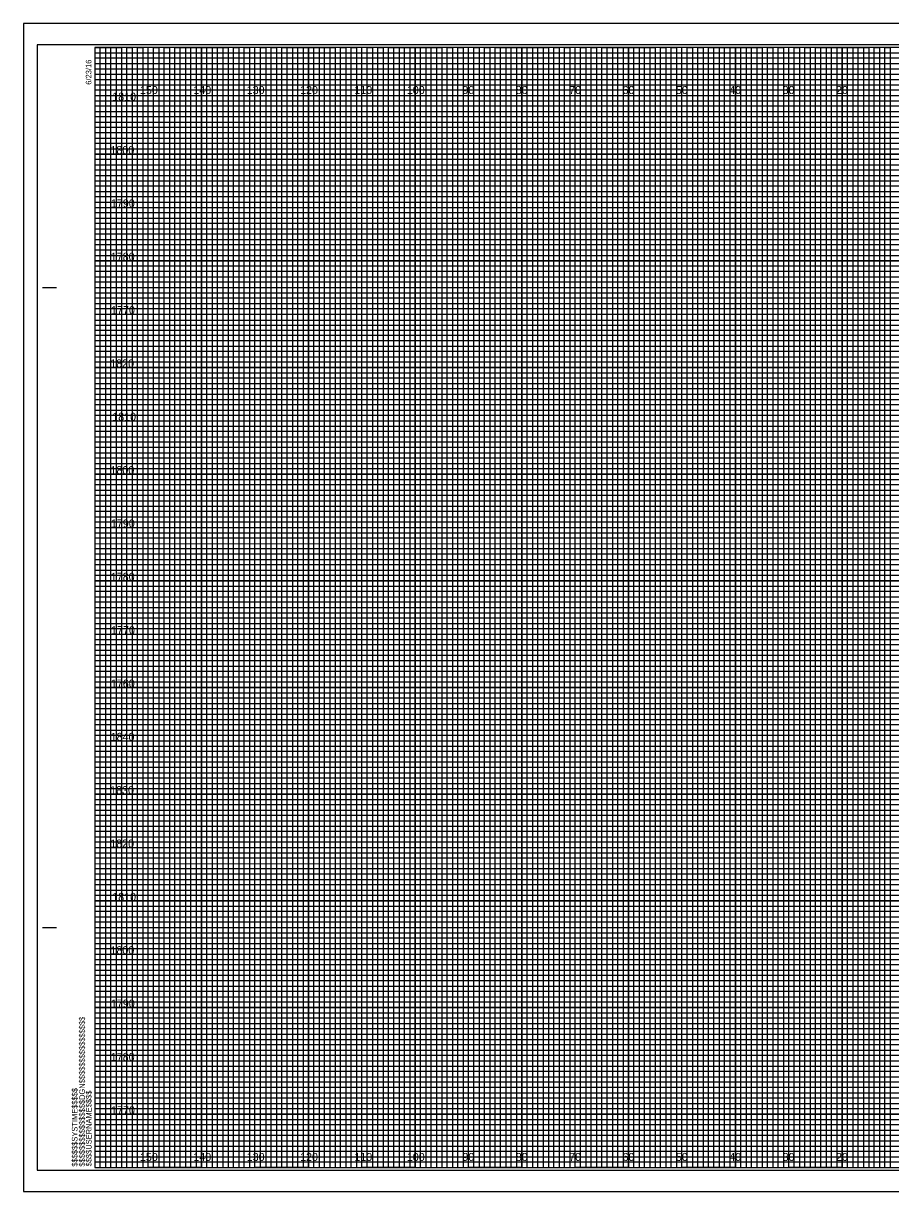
# Model space of a CAD drawing. Extents: x -163 to 174, y 11 to 1110.
# Drawn here: x -162.9 to -0.4, y 231.2 to 450.2 of the extents above; entities that cross this region are included whole.
import ezdxf

# ---------------------------------------------------------------- set-up
doc = ezdxf.new("R2010")
doc.units = 0
for name, color, linetype in [('Prop XS DDE', 7, 'Continuous'), ('Prop XS Earthwork Shape', 7, 'Continuous'), ('Prop XS Elevation Labels', 7, 'Continuous'), ('Sheet Cross Section CELL', 7, 'Continuous'), ('Sheet Cross Section Grid Middle CELL', 7, 'Continuous'), ('Sheet Cross Section Grid Minor 1 CELL', 7, 'Continuous'), ('Sheet Cross Section Grid Minor 2 CELL', 7, 'Continuous'), ('Sheet Cutting Line CELL', 7, 'Continuous'), ('Sheet DOT Grid CELL', 7, 'Continuous'), ('Sheet Plot Border Inside CELL', 7, 'Continuous'), ('Sheet Plot Border Outside CELL', 7, 'Continuous')]:
    doc.layers.add(name, color=color, linetype=linetype)

msp = doc.modelspace()

# ---------------------------------------------------------------- linework, layer by layer
at = {"layer": 'Prop XS DDE'}
for p, q in [((-139.53, 445.7), (-149.53, 445.7)), ((-139.53, 235.7), (-139.53, 445.7)), ((-119.53, 445.7), (-129.53, 445.7)), ((-129.53, 445.7), (-129.53, 235.7)), ((-119.53, 235.7), (-119.53, 445.7)), ((-99.53, 445.7), (-109.53, 445.7)), ((-109.53, 445.7), (-109.53, 235.7)), ((-99.53, 235.7), (-99.53, 445.7)), ((-79.53, 445.7), (-89.53, 445.7)), ((-89.53, 445.7), (-89.53, 235.7)), ((-79.53, 235.7), (-79.53, 445.7)), ((-59.53, 445.7), (-69.53, 445.7)), ((-69.53, 445.7), (-69.53, 235.7)), ((-59.53, 235.7), (-59.53, 445.7)), ((-39.53, 445.7), (-49.53, 445.7)), ((-49.53, 445.7), (-49.53, 235.7)), ((-39.53, 235.7), (-39.53, 445.7)), ((-19.53, 445.7), (-29.53, 445.7)), ((-29.53, 445.7), (-29.53, 235.7)), ((-19.53, 235.7), (-19.53, 445.7)), ((0.47, 445.7), (-9.53, 445.7)), ((-9.53, 445.7), (-9.53, 235.7)), ((-129.53, 235.7), (-139.53, 235.7)), ((-109.53, 235.7), (-119.53, 235.7)), ((-89.53, 235.7), (-99.53, 235.7)), ((-69.53, 235.7), (-79.53, 235.7)), ((-49.53, 235.7), (-59.53, 235.7)), ((-29.53, 235.7), (-39.53, 235.7)), ((-9.53, 235.7), (-19.53, 235.7))]:
    msp.add_line(p, q, dxfattribs=at)
for points in [[(-149.53, 435.7), (170.47, 435.7), (170.47, 425.7), (-149.53, 425.7)], [(-149.53, 415.7), (170.47, 415.7), (170.47, 405.7), (-149.53, 405.7)], [(-149.53, 395.7), (170.47, 395.7), (170.47, 385.7), (-149.53, 385.7)], [(-149.53, 375.7), (170.47, 375.7), (170.47, 365.7), (-149.53, 365.7)], [(-149.53, 355.7), (170.47, 355.7), (170.47, 345.7), (-149.53, 345.7)], [(-149.53, 335.7), (170.47, 335.7), (170.47, 325.7), (-149.53, 325.7)], [(-149.53, 315.7), (170.47, 315.7), (170.47, 305.7), (-149.53, 305.7)], [(-149.53, 295.7), (170.47, 295.7), (170.47, 285.7), (-149.53, 285.7)], [(-149.53, 275.7), (170.47, 275.7), (170.47, 265.7), (-149.53, 265.7)], [(-149.53, 255.7), (170.47, 255.7), (170.47, 245.7), (-149.53, 245.7)]]:
    msp.add_lwpolyline(points, dxfattribs=at)
at = {"layer": 'Sheet Cross Section CELL'}
for p, q in [((-159.33, 400.7), (-156.83, 400.7)), ((-159.23, 400.7), (-156.73, 400.7)), ((-159.33, 280.7), (-156.83, 280.7)), ((-159.23, 280.7), (-156.73, 280.7)), ((-149.53, 235.7), (-149.53, 235.7)), ((-149.53, 235.7), (-149.53, 235.7)), ((-149.53, 235.7), (-149.53, 235.7)), ((-149.53, 235.7), (-149.53, 235.7)), ((-149.53, 235.7), (-149.53, 235.7)), ((-149.53, 235.7), (-149.53, 235.7)), ((-149.53, 235.7), (-149.53, 235.7))]:
    msp.add_line(p, q, dxfattribs=at)
msp.add_lwpolyline([(170.47, 445.7), (-149.53, 445.7), (-149.53, 235.7), (170.47, 235.7)], close=True, dxfattribs=at)
at = {"layer": 'Sheet Cross Section Grid Middle CELL'}
for points in [[(-149.53, 445.7), (-144.53, 445.7), (-144.53, 235.7), (-134.53, 235.7), (-134.53, 445.7), (-124.53, 445.7), (-124.53, 235.7), (-114.53, 235.7), (-114.53, 445.7), (-104.53, 445.7), (-104.53, 235.7), (-94.53, 235.7), (-94.53, 445.7), (-84.53, 445.7), (-84.53, 235.7), (-74.53, 235.7), (-74.53, 445.7), (-64.53, 445.7), (-64.53, 235.7), (-54.53, 235.7), (-54.53, 445.7), (-44.53, 445.7), (-44.53, 235.7), (-34.53, 235.7), (-34.53, 445.7), (-24.53, 445.7), (-24.53, 235.7), (-14.53, 235.7), (-14.53, 445.7), (-4.53, 445.7), (-4.53, 235.7), (5.47, 235.7)], [(-149.53, 440.7), (125.47, 440.7)], [(-149.53, 420.7), (170.47, 420.7), (170.47, 430.7), (-149.53, 430.7)], [(-149.53, 400.7), (170.47, 400.7), (170.47, 410.7), (-149.53, 410.7)], [(-149.53, 380.7), (170.47, 380.7), (170.47, 390.7), (-149.53, 390.7)], [(-149.53, 360.7), (170.47, 360.7), (170.47, 370.7), (-149.53, 370.7)], [(-149.53, 340.7), (170.47, 340.7), (170.47, 350.7), (-149.53, 350.7)], [(-149.53, 320.7), (170.47, 320.7), (170.47, 330.7), (-149.53, 330.7)], [(-149.53, 300.7), (170.47, 300.7), (170.47, 310.7), (-149.53, 310.7)], [(-149.53, 280.7), (170.47, 280.7), (170.47, 290.7), (-149.53, 290.7)], [(-149.53, 260.7), (170.47, 260.7), (170.47, 270.7), (-149.53, 270.7)], [(-149.53, 240.7), (170.47, 240.7), (170.47, 250.7), (-149.53, 250.7)]]:
    msp.add_lwpolyline(points, dxfattribs=at)
at = {"layer": 'Sheet Cross Section Grid Minor 1 CELL'}
for p, q in [((-149.53, 444.7), (110.47, 444.7)), ((110.47, 443.68), (-149.53, 443.68)), ((-149.53, 443.68), (-149.53, 442.7)), ((-149.53, 442.7), (110.47, 442.7)), ((110.47, 441.59), (-149.53, 441.59)), ((-149.53, 441.59), (-149.53, 439.7)), ((-149.53, 439.7), (170.47, 439.7))]:
    msp.add_line(p, q, dxfattribs=at)
for points in [[(-149.53, 438.7), (120.47, 438.7), (170.47, 438.7), (170.47, 437.7), (-149.53, 437.7)], [(-149.53, 436.7), (170.47, 436.7), (170.47, 434.7), (-149.53, 434.7)], [(-149.53, 433.7), (170.47, 433.7), (170.47, 432.7), (-149.53, 432.68)], [(-149.53, 431.7), (170.47, 431.7), (170.47, 429.7), (-149.53, 429.7)], [(-149.53, 428.7), (170.47, 428.7), (170.47, 427.7), (-149.53, 427.7)], [(-149.53, 426.7), (170.47, 426.7), (170.47, 424.7), (-149.53, 424.7)], [(-149.53, 423.7), (170.47, 423.7), (170.47, 422.7), (-149.53, 422.7)], [(-149.53, 421.7), (170.47, 421.7), (170.47, 419.7), (-149.53, 419.7)], [(-149.53, 418.7), (170.47, 418.7), (170.47, 417.7), (-149.53, 417.7)], [(-149.53, 416.7), (170.47, 416.7), (170.47, 414.7), (-149.53, 414.7)], [(-149.53, 413.7), (170.47, 413.7), (170.47, 412.7), (-149.53, 412.7)], [(-149.53, 411.7), (170.47, 411.7), (170.47, 409.65), (170.47, 408.7), (170.47, 407.7), (-149.53, 407.7)], [(-149.53, 409.7), (170.47, 409.7), (170.47, 408.7), (-149.53, 408.7)], [(-149.53, 406.7), (170.47, 406.7), (170.47, 404.7), (-149.53, 404.73)], [(-149.53, 404.73), (170.47, 404.7), (170.47, 403.7), (-149.53, 403.7)], [(-149.53, 402.7), (170.47, 402.7), (170.47, 401.7), (-149.53, 401.7)], [(-149.53, 399.7), (170.47, 399.7), (170.47, 398.7), (-149.53, 398.7)], [(-149.53, 397.7), (170.47, 397.7), (170.47, 396.7), (-149.53, 396.7)], [(-149.6, 394.59), (170.47, 394.59), (170.47, 393.58), (-149.6, 393.58)], [(-149.53, 392.7), (170.47, 392.7), (170.47, 391.7), (-149.53, 391.7)], [(-149.53, 389.7), (170.47, 389.7), (170.47, 388.7), (-149.53, 388.7)], [(-149.53, 387.7), (170.47, 387.7), (170.47, 386.7), (-149.53, 386.7)], [(-149.53, 384.7), (170.47, 384.7), (170.47, 383.7), (-149.53, 383.7)], [(-149.53, 382.7), (170.47, 382.7), (170.47, 381.7), (-149.53, 381.7)], [(-149.53, 379.7), (170.47, 379.7), (170.47, 378.7), (-149.53, 378.7)], [(-149.53, 377.7), (170.47, 377.7), (170.47, 376.7), (-149.53, 376.7)], [(-149.53, 374.7), (170.47, 374.7), (170.46, 373.68), (-149.53, 373.7)], [(-149.53, 372.7), (170.47, 372.7), (170.47, 371.7), (-149.53, 371.7)], [(-149.53, 369.7), (170.47, 369.7), (170.47, 368.7), (-149.53, 368.7)], [(-149.53, 367.7), (170.47, 367.7), (170.47, 366.7), (-149.53, 366.7)], [(-149.53, 364.7), (170.47, 364.7), (170.47, 363.7), (-149.53, 363.7)], [(-149.53, 362.7), (170.47, 362.7), (170.47, 361.7), (-149.53, 361.7)], [(-149.53, 359.7), (170.47, 359.7), (170.47, 358.7), (-149.53, 358.7)], [(-149.53, 357.7), (170.47, 357.7), (170.47, 356.7), (-149.53, 356.7)], [(-149.53, 354.7), (170.47, 354.7), (170.47, 353.7), (-149.53, 353.7)], [(-149.53, 352.69), (170.54, 352.61), (170.47, 351.7), (-149.53, 351.7)], [(-149.53, 349.7), (170.47, 349.7), (170.47, 348.7), (-149.53, 348.7)], [(-149.53, 347.7), (170.47, 347.7), (170.47, 346.7), (-149.53, 346.7)], [(-149.53, 344.7), (170.47, 344.7), (170.47, 343.7), (-149.53, 343.7)], [(-149.53, 342.7), (170.47, 342.7), (170.47, 341.7), (-149.53, 341.7)], [(-149.53, 339.7), (170.47, 339.7), (170.47, 338.7), (-149.53, 338.7)], [(-149.53, 337.7), (170.47, 337.7), (170.47, 336.7), (-149.53, 336.7)], [(-149.53, 334.7), (170.47, 334.7), (170.47, 333.7), (-149.53, 333.7)], [(-149.53, 332.7), (170.47, 332.7), (170.47, 331.7), (-149.53, 331.7)], [(-149.53, 329.7), (170.47, 329.7), (170.47, 328.7), (-149.53, 328.7)], [(-149.53, 327.7), (170.47, 327.7), (170.47, 326.7), (-149.53, 326.7)], [(-149.53, 324.7), (170.47, 324.7), (170.47, 323.7), (-149.53, 323.7)], [(-149.53, 322.7), (170.47, 322.7), (170.47, 321.7), (-149.53, 321.7)], [(-149.53, 319.7), (170.47, 319.7), (170.47, 318.7), (-149.53, 318.7)], [(-149.53, 317.7), (170.47, 317.7), (170.47, 316.7), (-149.53, 316.7)], [(-149.53, 314.7), (170.47, 314.7), (170.46, 313.68), (-149.53, 313.7)], [(-149.53, 312.7), (170.47, 312.7), (170.47, 311.7), (-149.53, 311.7)], [(-149.53, 309.7), (170.47, 309.7), (170.47, 308.7), (-149.53, 308.7)], [(-149.53, 307.7), (170.47, 307.7), (170.47, 306.7), (-149.53, 306.7)], [(-149.53, 304.7), (170.47, 304.7), (170.47, 303.7), (-149.53, 303.7)], [(-149.53, 302.7), (170.47, 302.7), (170.47, 301.7), (-149.53, 301.7)], [(-149.53, 299.7), (170.47, 299.7), (170.47, 298.7), (-149.53, 298.7)], [(-149.53, 297.7), (170.47, 297.7), (170.47, 296.7), (-149.53, 296.7)], [(-149.53, 294.7), (170.47, 294.7), (170.47, 293.7), (-149.53, 293.7)], [(-149.53, 292.69), (170.54, 292.61), (170.47, 291.7), (-149.53, 291.7)], [(-149.53, 289.7), (170.47, 289.7), (170.47, 288.7), (-149.53, 288.7)], [(-149.53, 287.7), (170.47, 287.7), (170.47, 286.7), (-149.53, 286.7)], [(-149.53, 284.7), (170.47, 284.7), (170.47, 283.7), (-149.53, 283.7)], [(-149.53, 282.7), (170.47, 282.7), (170.47, 281.7), (-149.53, 281.7)], [(-149.53, 279.7), (170.47, 279.7), (170.47, 278.7), (-149.53, 278.7)], [(-149.53, 277.7), (170.47, 277.7), (170.47, 276.7), (-149.53, 276.7)], [(-149.53, 274.7), (170.47, 274.7), (170.47, 273.7), (-149.53, 273.7)], [(-149.53, 272.7), (170.47, 272.7), (170.47, 271.7), (-149.53, 271.7)], [(-149.53, 269.7), (170.47, 269.7), (170.47, 268.7), (-149.53, 268.7)], [(-149.53, 267.7), (170.47, 267.7), (170.47, 266.7), (-149.53, 266.7)], [(-149.53, 264.7), (170.47, 264.7), (170.47, 263.7), (-149.53, 263.7)], [(-149.53, 262.7), (170.47, 262.7), (170.47, 261.7), (-149.53, 261.7)], [(-149.53, 259.7), (170.47, 259.7), (170.47, 258.7), (-149.53, 258.7)], [(-149.53, 257.7), (170.47, 257.7), (170.47, 256.7), (-149.53, 256.7)], [(-149.53, 254.7), (170.47, 254.7), (170.47, 253.7), (-149.53, 253.7)], [(-149.53, 252.7), (170.47, 252.7), (170.47, 251.7), (-149.53, 251.7)], [(-149.53, 249.7), (170.47, 249.7), (170.47, 248.7), (-149.53, 248.7)], [(-149.53, 247.7), (170.47, 247.7), (170.47, 246.7), (-149.53, 246.7)], [(-149.53, 244.7), (170.47, 244.7), (170.47, 243.7), (-149.53, 243.7)], [(-149.53, 242.7), (170.47, 242.7), (170.47, 241.7), (-149.53, 241.7)], [(-149.53, 239.7), (170.47, 239.7), (170.47, 238.7), (-149.53, 238.7)], [(-149.53, 237.7), (170.47, 237.7), (170.47, 236.7), (-149.53, 236.7)]]:
    msp.add_lwpolyline(points, dxfattribs=at)
at = {"layer": 'Sheet Cross Section Grid Minor 2 CELL'}
for points in [[(-149.53, 235.7), (-148.53, 235.7), (-148.53, 445.7), (-147.53, 445.7), (-147.53, 235.7)], [(-147.53, 235.7), (-146.53, 235.7), (-146.53, 445.7), (-145.53, 445.7), (-145.53, 235.7)], [(-144.53, 235.7), (-143.53, 235.7), (-143.53, 445.7), (-142.53, 445.7), (-142.53, 235.7)], [(-142.53, 235.7), (-141.53, 235.7), (-141.53, 445.7), (-140.53, 445.7), (-140.53, 235.7)], [(-139.53, 235.7), (-138.53, 235.7), (-138.53, 445.7), (-137.53, 445.7), (-137.53, 235.7)], [(-137.53, 235.7), (-136.53, 235.7), (-136.53, 445.7), (-135.53, 445.7), (-135.53, 235.7)], [(-134.53, 235.7), (-133.53, 235.7), (-133.53, 445.7), (-132.53, 445.7), (-132.53, 235.7)], [(-132.53, 235.7), (-131.53, 235.7), (-131.53, 445.7), (-130.53, 445.7), (-130.53, 235.7)], [(-129.53, 235.7), (-128.53, 235.7), (-128.53, 445.7), (-127.53, 445.7), (-127.53, 235.7)], [(-127.53, 235.7), (-126.53, 235.7), (-126.53, 445.7), (-125.53, 445.7), (-125.53, 235.7)], [(-124.53, 235.7), (-123.53, 235.7), (-123.53, 445.7), (-122.53, 445.7), (-122.53, 235.7)], [(-122.53, 235.7), (-121.53, 235.7), (-121.53, 445.7), (-120.53, 445.7), (-120.53, 235.7)], [(-119.53, 235.7), (-118.53, 235.7), (-118.53, 445.7), (-117.53, 445.7), (-117.53, 235.7)], [(-117.53, 235.7), (-116.53, 235.7), (-116.53, 445.7), (-115.53, 445.7), (-115.53, 235.7)], [(-114.53, 235.7), (-113.53, 235.7), (-113.53, 445.7), (-112.53, 445.7), (-112.53, 235.7)], [(-112.53, 235.7), (-111.53, 235.7), (-111.53, 445.7), (-110.53, 445.7), (-110.53, 235.7)], [(-109.53, 235.7), (-108.53, 235.7), (-108.53, 445.7), (-107.53, 445.7), (-107.53, 235.7)], [(-107.53, 235.7), (-106.53, 235.7), (-106.53, 445.7), (-105.53, 445.7), (-105.53, 235.7)], [(-104.53, 235.7), (-103.53, 235.7), (-103.53, 445.7), (-102.53, 445.7), (-102.53, 235.7)], [(-102.53, 235.7), (-101.53, 235.7), (-101.53, 445.7), (-100.53, 445.7), (-100.53, 235.7)], [(-99.53, 235.7), (-98.53, 235.7), (-98.53, 445.7), (-97.53, 445.7), (-97.53, 235.7)], [(-97.53, 235.7), (-96.53, 235.7), (-96.53, 445.7), (-95.53, 445.7), (-95.53, 235.7)], [(-94.53, 235.7), (-93.53, 235.7), (-93.53, 445.7), (-92.53, 445.7), (-92.53, 235.7)], [(-92.53, 235.7), (-91.53, 235.7), (-91.53, 445.7), (-90.53, 445.7), (-90.53, 235.7)], [(-89.53, 235.7), (-88.53, 235.7), (-88.53, 445.7), (-87.53, 445.7), (-87.53, 235.7)], [(-87.53, 235.7), (-86.53, 235.7), (-86.53, 445.7), (-85.53, 445.7), (-85.53, 235.7)], [(-84.53, 235.7), (-83.53, 235.7), (-83.53, 445.7), (-82.53, 445.7), (-82.53, 235.7)], [(-82.53, 235.7), (-81.53, 235.7), (-81.53, 445.7), (-80.53, 445.7), (-80.53, 235.7)], [(-79.53, 235.7), (-78.53, 235.7), (-78.53, 445.7), (-77.53, 445.7), (-77.53, 235.7)], [(-77.53, 235.7), (-76.53, 235.7), (-76.53, 445.7), (-75.53, 445.7), (-75.53, 235.7)], [(-74.53, 235.7), (-73.53, 235.7), (-73.53, 445.7), (-72.53, 445.7), (-72.53, 235.7)], [(-72.53, 235.7), (-71.53, 235.7), (-71.53, 445.7), (-70.53, 445.7), (-70.53, 235.7)], [(-69.53, 235.7), (-68.53, 235.7), (-68.53, 445.7), (-67.53, 445.7), (-67.53, 235.7)], [(-67.53, 235.7), (-66.53, 235.7), (-66.53, 445.7), (-65.53, 445.7), (-65.53, 235.7)], [(-64.53, 235.7), (-63.53, 235.7), (-63.53, 445.7), (-62.53, 445.7), (-62.53, 235.7)], [(-62.53, 235.7), (-61.53, 235.7), (-61.53, 445.7), (-60.53, 445.7), (-60.53, 235.7)], [(-59.53, 235.7), (-58.53, 235.7), (-58.53, 445.7), (-57.53, 445.7), (-57.53, 235.7)], [(-57.53, 235.7), (-56.53, 235.7), (-56.53, 445.7), (-55.53, 445.7), (-55.53, 235.7)], [(-54.53, 235.7), (-53.53, 235.7), (-53.53, 445.7), (-52.53, 445.7), (-52.53, 235.7)], [(-52.53, 235.7), (-51.53, 235.7), (-51.53, 445.7), (-50.53, 445.7), (-50.53, 235.7)], [(-49.53, 235.7), (-48.53, 235.7), (-48.53, 445.7), (-47.53, 445.7), (-47.53, 235.7)], [(-47.53, 235.7), (-46.53, 235.7), (-46.53, 445.7), (-45.53, 445.7), (-45.53, 235.7)], [(-44.53, 235.7), (-43.53, 235.7), (-43.53, 445.7), (-42.53, 445.7), (-42.53, 235.7)], [(-42.53, 235.7), (-41.53, 235.7), (-41.53, 445.7), (-40.53, 445.7), (-40.53, 235.7)], [(-39.53, 235.7), (-38.53, 235.7), (-38.53, 445.7), (-37.53, 445.7), (-37.53, 235.7)], [(-37.53, 235.7), (-36.53, 235.7), (-36.53, 445.7), (-35.53, 445.7), (-35.53, 235.7)], [(-34.53, 235.7), (-33.53, 235.7), (-33.53, 445.7), (-32.53, 445.7), (-32.53, 235.7)], [(-32.53, 235.7), (-31.53, 235.7), (-31.53, 445.7), (-30.53, 445.7), (-30.53, 235.7)], [(-29.53, 235.7), (-28.53, 235.7), (-28.53, 445.7), (-27.53, 445.7), (-27.53, 235.7)], [(-27.53, 235.7), (-26.53, 235.7), (-26.53, 445.7), (-25.53, 445.7), (-25.53, 235.7)], [(-24.53, 235.7), (-23.53, 235.7), (-23.53, 445.7), (-22.53, 445.7), (-22.53, 235.7)], [(-22.53, 235.7), (-21.53, 235.7), (-21.53, 445.7), (-20.53, 445.7), (-20.53, 235.7)], [(-19.53, 235.7), (-18.53, 235.7), (-18.53, 445.7), (-17.53, 445.7), (-17.53, 235.7)], [(-17.53, 235.7), (-16.53, 235.7), (-16.53, 445.7), (-15.53, 445.7), (-15.53, 235.7)], [(-14.53, 235.7), (-13.53, 235.7), (-13.53, 445.7), (-12.53, 445.7), (-12.53, 235.7)], [(-12.53, 235.7), (-11.53, 235.7), (-11.53, 445.7), (-10.53, 445.7), (-10.53, 235.7)], [(-9.53, 235.7), (-8.53, 235.7), (-8.53, 445.7), (-7.53, 445.7), (-7.53, 235.7)], [(-7.53, 235.7), (-6.53, 235.7), (-6.53, 445.7), (-5.53, 445.7), (-5.53, 235.7)], [(-4.53, 235.7), (-3.53, 235.7), (-3.53, 445.7), (-2.53, 445.7), (-2.53, 235.7)], [(-2.53, 235.7), (-1.53, 235.7), (-1.53, 445.7), (-0.53, 445.7), (-0.53, 235.7)]]:
    msp.add_lwpolyline(points, dxfattribs=at)
at = {"layer": 'Sheet Cutting Line CELL'}
for p, q in [((173.77, 450.2), (-162.93, 450.2)), ((-162.93, 450.2), (-162.93, 231.2)), ((-162.93, 231.2), (173.77, 231.2))]:
    msp.add_line(p, q, dxfattribs=at)
at = {"layer": 'Sheet DOT Grid CELL'}
for p, q in [((-139.53, 235.7), (-139.53, 445.7)), ((-129.53, 235.7), (-129.53, 445.7)), ((-119.53, 235.7), (-119.53, 445.7)), ((-109.53, 235.7), (-109.53, 445.7)), ((-99.53, 235.7), (-99.53, 445.7)), ((-89.53, 235.7), (-89.53, 445.7)), ((-79.53, 235.7), (-79.53, 445.7)), ((-69.53, 235.7), (-69.53, 445.7)), ((-59.53, 235.7), (-59.53, 445.7)), ((-49.53, 235.7), (-49.53, 445.7)), ((-39.53, 235.7), (-39.53, 445.7)), ((-29.53, 235.7), (-29.53, 445.7)), ((-19.53, 235.7), (-19.53, 445.7)), ((-9.53, 235.7), (-9.53, 445.7)), ((-149.53, 435.7), (170.47, 435.7)), ((-149.53, 425.7), (170.47, 425.7)), ((-149.53, 415.7), (170.47, 415.7)), ((-149.53, 405.7), (170.47, 405.7)), ((-149.53, 395.7), (170.47, 395.7)), ((-149.53, 385.7), (170.47, 385.7)), ((-149.53, 375.7), (170.47, 375.7)), ((-149.53, 365.7), (170.47, 365.7)), ((-149.53, 355.7), (170.47, 355.7)), ((-149.53, 345.7), (170.47, 345.7)), ((-149.53, 335.7), (170.47, 335.7)), ((-149.53, 325.7), (170.47, 325.7)), ((-149.53, 315.7), (170.47, 315.7)), ((-149.53, 305.7), (170.47, 305.7)), ((-149.53, 295.7), (170.47, 295.7)), ((-149.53, 285.7), (170.47, 285.7)), ((-149.53, 275.7), (170.47, 275.7)), ((-149.53, 265.7), (170.47, 265.7)), ((-149.53, 255.7), (170.47, 255.7)), ((-149.53, 245.7), (170.47, 245.7))]:
    msp.add_line(p, q, dxfattribs=at)
at = {"layer": 'Sheet Plot Border Inside CELL'}
msp.add_lwpolyline([(-160.33, 235.2), (172.87, 235.2), (172.87, 446.2), (-160.33, 446.2)], close=True, dxfattribs=at)
at = {"layer": 'Sheet Plot Border Outside CELL'}
msp.add_lwpolyline([(-162.93, 231.2), (173.77, 231.2), (173.77, 450.2), (-162.93, 450.2)], close=True, dxfattribs=at)

# ---------------------------------------------------------------- texts
at = {"layer": 'Prop XS Earthwork Shape'}
for s, p in [('150', (-141.08, 436.95)), ('140', (-131.08, 436.95)), ('130', (-121.08, 436.95)), ('120', (-111.08, 436.95)), ('110', (-100.91, 436.95)), ('100', (-91.08, 436.95)), ('90', (-80.67, 436.95)), ('80', (-70.67, 436.95)), ('70', (-60.67, 436.95)), ('60', (-50.67, 436.95)), ('50', (-40.67, 436.95)), ('40', (-30.67, 436.95)), ('30', (-20.67, 436.95)), ('20', (-10.67, 436.95)), ('150', (-141.08, 236.95)), ('140', (-131.08, 236.95)), ('130', (-121.08, 236.95)), ('120', (-111.08, 236.95)), ('110', (-100.91, 236.95)), ('100', (-91.08, 236.95)), ('90', (-80.67, 236.95)), ('80', (-70.67, 236.95)), ('70', (-60.67, 236.95)), ('60', (-50.67, 236.95)), ('50', (-40.67, 236.95)), ('40', (-30.67, 236.95)), ('30', (-20.67, 236.95)), ('20', (-10.67, 236.95))]:
    msp.add_text(s, height=1.5, dxfattribs=at).set_placement(p)
at = {"layer": 'Prop XS Elevation Labels'}
for s, p in [('1810', (-146.28, 435.7)), ('1800', (-146.61, 425.7)), ('1790', (-146.53, 415.7)), ('1780', (-146.55, 405.7)), ('1770', (-146.49, 395.7)), ('1820', (-146.65, 385.7)), ('1810', (-146.28, 375.7)), ('1800', (-146.61, 365.7)), ('1790', (-146.53, 355.7)), ('1780', (-146.55, 345.7)), ('1770', (-146.49, 335.7)), ('1760', (-146.53, 325.7)), ('1840', (-146.58, 315.7)), ('1830', (-146.67, 305.7)), ('1820', (-146.65, 295.7)), ('1810', (-146.28, 285.7)), ('1800', (-146.61, 275.7)), ('1790', (-146.53, 265.7)), ('1780', (-146.55, 255.7)), ('1770', (-146.49, 245.7))]:
    msp.add_text(s, height=1.5, dxfattribs=at).set_placement(p)
at = {"layer": 'Sheet Cross Section CELL'}
for s, p in [('6/23/16', (-150.18, 438.7)), ('$$$$$$$$$$$$$$$$DGN$$$$$$$$$$$$$$$$', (-151.41, 235.88)), ('$$$$$$SYSTIME$$$$$', (-152.79, 235.88)), ('$$$$USERNAME$$$$', (-150.15, 235.93))]:
    msp.add_text(s, height=1.05, rotation=90, dxfattribs=at).set_placement(p)

doc.saveas('drawing.dxf')
